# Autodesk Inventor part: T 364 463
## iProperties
Company: Mayer & Müller AG Schaltgeräte
Created: 2006-03
Part Number: T 364 463
Material: 1.4301
Document SubType Name: Modeling
Designer: I.Baliuc
Description: Grundplatte
Density: 7.86 g/cm^3
Author: T.Messerschmitt
Keywords: 364409
Revision Number: 364463
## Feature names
1. Bohrung_M12 [Hole]
2. Bezeichnung2 [Tagging]
